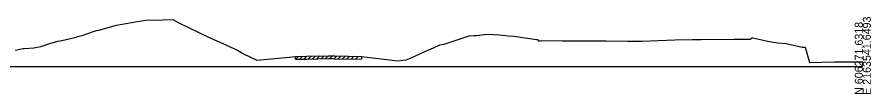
# Model space of a CAD drawing. Extents: x -26 to 6803, y -10 to 19606.
# Drawn here: x 6504.2 to 6802.8, y 5490.3 to 5517.3 of the extents above; entities that cross this region are included whole.
import ezdxf

# ---------------------------------------------------------------- set-up
doc = ezdxf.new("R2010")
doc.units = 0
for name, color, linetype in [('RD_GPK_XS_Cell', 7, 'Continuous'), ('RD_XS_ExGround', 7, 'Continuous'), ('RD_XS_ExPaveRet', 7, 'Continuous')]:
    doc.layers.add(name, color=color, linetype=linetype)

msp = doc.modelspace()

# ---------------------------------------------------------------- linework, layer by layer
at = {"layer": 'RD_GPK_XS_Cell'}
msp.add_line((6400, 5500), (6800, 5500), dxfattribs=at)
at = {"layer": 'RD_XS_ExGround'}
msp.add_lwpolyline([(6503.51, 5505.64), (6506.29, 5506.24), (6506.67, 5506.28), (6510.09, 5506.52), (6512.54, 5506.97), (6515.65, 5507.99), (6518.5, 5508.81), (6519.31, 5508.97), (6521.95, 5509.56), (6524.82, 5510.19), (6525.44, 5510.5), (6527.28, 5510.91), (6530.98, 5512.18), (6531.99, 5512.54), (6532.81, 5512.76), (6538.95, 5514.51), (6546.21, 5515.72), (6549.23, 5516.22), (6555.33, 5516.35), (6558.64, 5516.42), (6560.8, 5515.31), (6570.94, 5510.38), (6571.98, 5509.93), (6577.46, 5507.49), (6581.26, 5505.72), (6583.45, 5504.44), (6588.02, 5502.12), (6599.43, 5503.27), (6600.46, 5503.37), (6601.56, 5503.48), (6605.57, 5503.57), (6613.27, 5503.74), (6614.77, 5503.72), (6615.39, 5503.69), (6624.71, 5503.5), (6635.46, 5502.19), (6637.41, 5501.95), (6639.14, 5502.14), (6640.29, 5502.28), (6642.05, 5503.04), (6646.56, 5505.05), (6649.87, 5506.51), (6652.11, 5507.51), (6653.63, 5507.83), (6662.35, 5510.68), (6663.98, 5510.82), (6664.86, 5510.8), (6668.5, 5511.27), (6672.96, 5511.07), (6675.95, 5510.77), (6677.94, 5510.62), (6685.88, 5509.47), (6686.32, 5509.48), (6686.5, 5508.98), (6687.01, 5509.01), (6687.76, 5509.06), (6694.99, 5509.01), (6697.21, 5509.01), (6704.15, 5508.93), (6705.63, 5508.92), (6706.82, 5509.01), (6710.19, 5508.96), (6717.67, 5508.89), (6719.46, 5508.85), (6720.28, 5508.8), (6722.89, 5508.82), (6734.28, 5509.31), (6740.47, 5509.41), (6743.04, 5509.48), (6743.47, 5509.48), (6754.96, 5509.55), (6758.5, 5509.57), (6759.63, 5509.58), (6760.52, 5509.55), (6760.87, 5509.53), (6761.06, 5510.03), (6761.49, 5510.03), (6764.7, 5509.29), (6766.66, 5508.88), (6770.19, 5508.31), (6773.19, 5507.97), (6778.78, 5506.79), (6779.35, 5506.79), (6779.82, 5506.79), (6781.32, 5501.34), (6790.14, 5501.58), (6791.94, 5501.63), (6799.17, 5501.64), (6800, 5501.63)], dxfattribs=at)
at = {"layer": 'RD_XS_ExPaveRet'}
for p, q in [((6601.56, 5502.48), (6602.58, 5503.51)), ((6601.56, 5502.48), (6601.56, 5503.48)), ((6601.56, 5502.48), (6605.57, 5502.57)), ((6601.56, 5502.48), (6601.56, 5502.48)), ((6603.06, 5502.52), (6604.08, 5503.54)), ((6604.56, 5502.55), (6605.58, 5503.57)), ((6605.57, 5502.57), (6613.27, 5502.74)), ((6606.06, 5502.58), (6607.08, 5503.6)), ((6607.56, 5502.61), (6608.58, 5503.63)), ((6609.06, 5502.65), (6610.08, 5503.67)), ((6610.56, 5502.68), (6611.58, 5503.7)), ((6612.06, 5502.71), (6613.08, 5503.73)), ((6613.27, 5502.74), (6614.77, 5502.72)), ((6613.56, 5502.73), (6614.54, 5503.72)), ((6614.77, 5502.72), (6615.39, 5502.69)), ((6615.06, 5502.7), (6616.03, 5503.68)), ((6615.39, 5502.69), (6624.71, 5502.5)), ((6616.56, 5502.67), (6617.54, 5503.65)), ((6618.06, 5502.63), (6619.04, 5503.61)), ((6619.56, 5502.6), (6620.54, 5503.58)), ((6621.06, 5502.57), (6622.04, 5503.55)), ((6622.56, 5502.54), (6623.54, 5503.52)), ((6624.71, 5503.5), (6624.71, 5502.5)), ((6624.71, 5502.5), (6624.71, 5502.5))]:
    msp.add_line(p, q, dxfattribs=at)

# ---------------------------------------------------------------- texts
at = {"layer": 'RD_GPK_XS_Cell'}
for s, p in [('E 2163541.6493', (6802.8, 5490)), ('N 606271.6318', (6800, 5490))]:
    msp.add_text(s, height=2.8, rotation=90, dxfattribs=at).set_placement(p)

doc.saveas('drawing.dxf')
